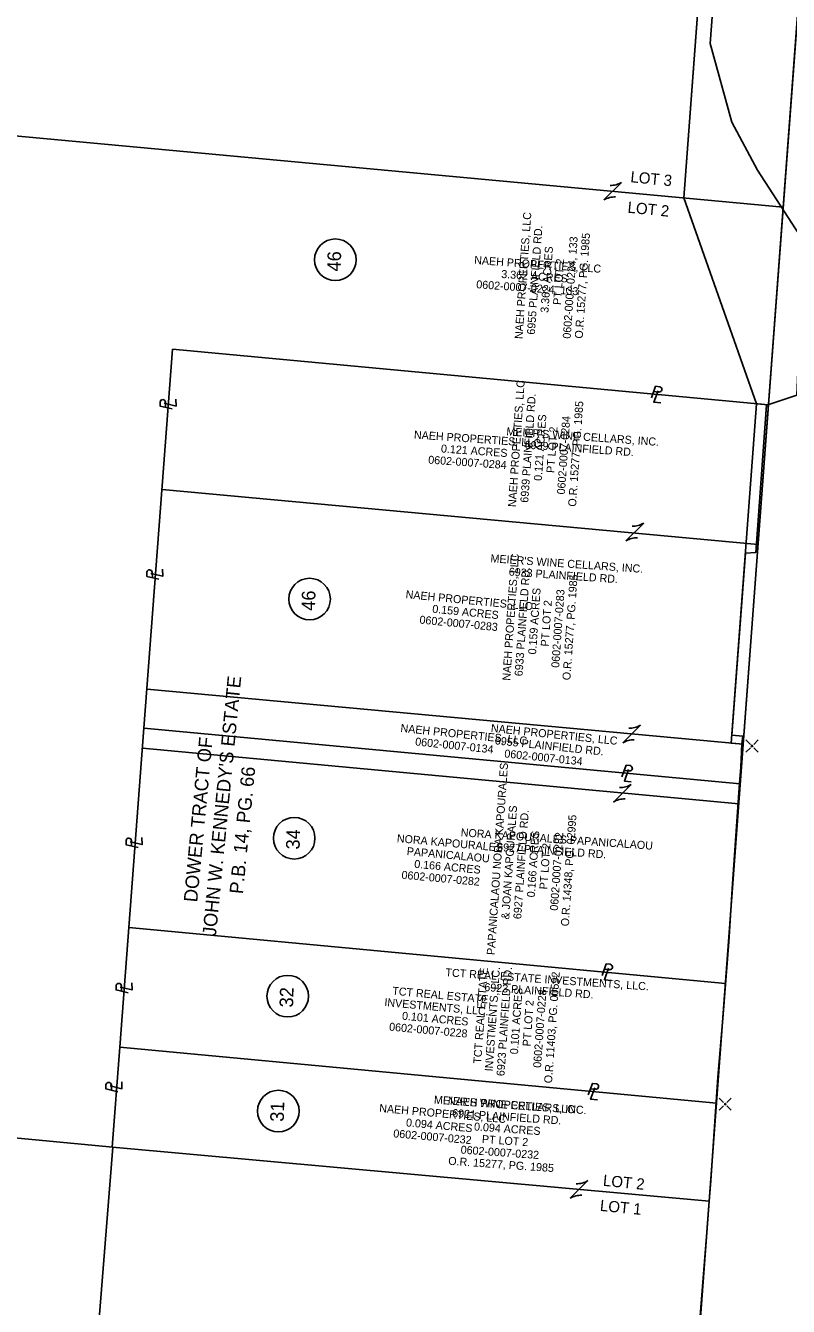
# Model space of a CAD drawing. Extents: x 204354 to 231038, y 361459 to 365260.
# Drawn here: x 220388.1 to 220578.9, y 362494.1 to 362814.2 of the extents above; entities that cross this region are included whole.
import ezdxf

# ---------------------------------------------------------------- set-up
doc = ezdxf.new("R2010")
doc.units = 0
for name, color, linetype in [('CM_Corridor_Point_Control', 7, 'Continuous'), ('Default', 7, 'Continuous'), ('DT_P_Contour_Minor', 7, 'Continuous'), ('DT_P_Contour_Text', 7, 'Continuous'), ('DT_P_Triangles', 7, 'Continuous'), ('DT_X_Contour_Minor', 7, 'Continuous'), ('MD_P_Intersection_MatchLine', 7, 'Continuous'), ('MD_P_Surface_Asphalt_Concrete_Base', 7, 'Continuous'), ('MD_P_SW_BOT', 7, 'Continuous'), ('PV_P_Walk', 7, 'Continuous'), ('SC_Shading1', 7, 'Continuous')]:
    doc.layers.add(name, color=color, linetype=linetype)

msp = doc.modelspace()

# ---------------------------------------------------------------- linework, layer by layer
at = {"layer": 'DT_P_Contour_Text'}
for centre in [(220465.57, 362755.66), (220459.14, 362670.86), (220455.29, 362611.08), (220453.67, 362571.61), (220451.33, 362542.88)]:
    msp.add_circle(centre, 5.2, dxfattribs=at)
at = {"layer": 'DT_P_Triangles'}
msp.add_lwpolyline([(220574.42, 363010.6), (220559.33, 362809.74), (220564.76, 362790.07), (220571.14, 362778.03), (220582.68, 362760.32), (220581, 362721.86), (220574.51, 362719.65), (220573.39, 362719.33), (220570.75, 362682.52), (220568.14, 362682.31), (220564.75, 362636.86), (220567.45, 362636.61), (220567.26, 362634.64), (220567.01, 362628.84), (220566.63, 362624.87), (220564.92, 362599.67), (220563.95, 362585.17), (220562.45, 362566.05), (220561.26, 362551.34), (220559.45, 362525.52), (220558.99, 362519.33), (220558.41, 362511.57), (220556.32, 362485.49)], dxfattribs=at)
at = {"layer": 'MD_P_Intersection_MatchLine'}
for p, q in [((220552.71, 362771.16), (220570.06, 363003.79)), ((220552.71, 362771.16), (220570.93, 362719.68)), ((220573.92, 362719.4), (220570.93, 362719.68))]:
    msp.add_line(p, q, dxfattribs=at)
at = {"layer": 'MD_P_Surface_Asphalt_Concrete_Base'}
for p, q in [((220568.27, 362635.64), (220569.37, 362634.55)), ((220570.2, 362634.55), (220571.29, 362635.64)), ((220568.27, 362632.62), (220569.37, 362633.72)), ((220570.2, 362633.72), (220571.29, 362632.62)), ((220561.57, 362546.12), (220562.66, 362545.03)), ((220563.49, 362545.03), (220564.58, 362546.12)), ((220561.57, 362543.1), (220562.66, 362544.19)), ((220563.49, 362544.19), (220564.58, 362543.1))]:
    msp.add_line(p, q, dxfattribs=at)
for centre in [(220569.78, 362634.14), (220563.08, 362544.62)]:
    msp.add_circle(centre, 0.17, dxfattribs=at)
at = {"layer": 'MD_P_SW_BOT'}
for p, q in [((220577.61, 362768.85), (220225.01, 362801.43)), ((220532.75, 362770.61), (220537.17, 362775.02)), ((220534.96, 362772.81), (220534.96, 362772.81)), ((220424.82, 362733.35), (220417.69, 362638.61)), ((220573.92, 362719.4), (220424.82, 362733.35)), ((220545.18, 362722.72), (220546.47, 362722.6)), ((220545.92, 362722.02), (220545.92, 362722.02)), ((220423.14, 362718.76), (220423.11, 362720.05)), ((220423.74, 362719.57), (220423.74, 362719.57)), ((220571.31, 362684.5), (220422.28, 362698.27)), ((220538.26, 362685.43), (220542.69, 362689.84)), ((220540.48, 362687.64), (220540.48, 362687.64)), ((220419.82, 362676.2), (220419.78, 362677.5)), ((220420.42, 362677.02), (220420.42, 362677.02)), ((220567.59, 362634.61), (220418.56, 362648.38)), ((220411.68, 362558.84), (220417.69, 362638.61)), ((220417.69, 362638.61), (220566.85, 362624.67)), ((220537.44, 362634.94), (220541.87, 362639.35)), ((220539.65, 362637.15), (220539.65, 362637.15)), ((220417.31, 362633.63), (220566.47, 362619.68)), ((220537.82, 362628.01), (220539.11, 362627.89)), ((220538.56, 362627.31), (220538.56, 362627.31)), ((220535.14, 362620.13), (220539.57, 362624.54)), ((220537.36, 362622.33), (220537.36, 362622.33)), ((220414.64, 362609.15), (220414.61, 362610.44)), ((220415.24, 362609.97), (220415.24, 362609.97)), ((220563.16, 362574.8), (220413.94, 362588.75)), ((220532.83, 362578.33), (220534.12, 362578.21)), ((220533.57, 362577.64), (220533.57, 362577.64)), ((220412.14, 362572.84), (220412.1, 362574.13)), ((220412.74, 362573.65), (220412.74, 362573.65)), ((220146.03, 362558.58), (220409.9, 362533.9)), ((220411.68, 362558.84), (220409.8, 362533.91)), ((220560.9, 362544.89), (220411.68, 362558.84)), ((220409.6, 362548.1), (220409.57, 362549.4)), ((220410.2, 362548.92), (220410.2, 362548.92)), ((220529.37, 362548.46), (220530.66, 362548.34)), ((220530.11, 362547.77), (220530.11, 362547.77)), ((220409.9, 362533.9), (220398.1, 362383.18)), ((220409.82, 362533.91), (220559.06, 362520.33)), ((220524.3, 362521.08), (220528.72, 362525.5)), ((220526.51, 362523.29), (220526.51, 362523.29))]:
    msp.add_line(p, q, dxfattribs=at)
for points in [[(220544.61, 362721.17), (220545.66, 362724.05), (220546.69, 362723.95)], [(220422.78, 362719.81), (220425.76, 362719.11), (220425.71, 362720.85)], [(220546.27, 362722.95), (220545.21, 362720.08), (220546.95, 362719.92)], [(220424.75, 362718.38), (220421.76, 362719.08), (220421.73, 362720.11)], [(220421.42, 362675.83), (220418.44, 362676.53), (220418.41, 362677.56)], [(220419.45, 362677.26), (220422.43, 362676.56), (220422.38, 362678.3)], [(220537.26, 362626.46), (220538.31, 362629.34), (220539.34, 362629.24)], [(220538.92, 362628.24), (220537.85, 362625.37), (220539.59, 362625.21)], [(220416.25, 362608.77), (220413.26, 362609.47), (220413.23, 362610.5)], [(220414.28, 362610.21), (220417.26, 362609.5), (220417.2, 362611.25)], [(220532.27, 362576.78), (220533.32, 362579.66), (220534.35, 362579.57)], [(220533.93, 362578.57), (220532.86, 362575.7), (220534.6, 362575.53)], [(220413.74, 362572.46), (220410.75, 362573.16), (220410.73, 362574.19)], [(220411.77, 362573.89), (220414.75, 362573.19), (220414.7, 362574.93)], [(220411.21, 362547.73), (220408.22, 362548.43), (220408.19, 362549.46)], [(220409.24, 362549.16), (220412.21, 362548.46), (220412.16, 362550.2)], [(220528.8, 362546.92), (220529.86, 362549.8), (220530.88, 362549.7)], [(220530.46, 362548.7), (220529.4, 362545.83), (220531.14, 362545.66)]]:
    msp.add_lwpolyline(points, dxfattribs=at)
for centre, radius, start, end in [((220534.42, 362779.59), 5.34, 268.4155, 301.058), ((220535.5, 362766.04), 5.34, 88.4155, 121.058), ((220546.53, 362723.28), 0.69, 265.1289, 75.986), ((220422.42, 362720.03), 0.69, 2.1187, 172.9759), ((220539.93, 362694.42), 5.34, 268.4155, 301.058), ((220541.02, 362680.86), 5.34, 88.4155, 121.058), ((220419.09, 362677.48), 0.69, 2.1187, 172.9759), ((220539.11, 362643.93), 5.34, 268.4155, 301.058), ((220540.19, 362630.37), 5.34, 88.4155, 121.058), ((220539.17, 362628.57), 0.69, 265.1289, 75.986), ((220536.81, 362629.11), 5.34, 268.4155, 301.058), ((220537.9, 362615.56), 5.34, 88.4155, 121.058), ((220413.92, 362610.42), 0.69, 2.1187, 172.9759), ((220534.18, 362578.9), 0.69, 265.1289, 75.986), ((220411.41, 362574.11), 0.69, 2.1187, 172.9759), ((220408.88, 362549.37), 0.69, 2.1187, 172.9759), ((220530.72, 362549.03), 0.69, 265.1289, 75.986), ((220525.96, 362530.07), 5.34, 268.4961, 301.1387), ((220527.06, 362516.52), 5.34, 88.4961, 121.1387)]:
    msp.add_arc(centre, radius, start, end, dxfattribs=at)
at = {"layer": 'PV_P_Walk'}
msp.add_line((220534.47, 362190.67), (220633.24, 363514.5), dxfattribs=at)
at = {"layer": 'SC_Shading1'}
for points in [[(220573.92, 362719.4), (220570.93, 362719.68), (220552.71, 362771.16), (220570.06, 363003.79), (220594.96, 363001.49)], [(220567.59, 362634.61), (220564.6, 362634.88), (220570.93, 362719.68), (220573.92, 362719.4)]]:
    msp.add_lwpolyline(points, close=True, dxfattribs=at)

# ---------------------------------------------------------------- texts
at = {"layer": 'CM_Corridor_Point_Control'}
for s, p in [("MEIER'S WINE CELLARS, INC.", (220508.3, 362711.81)), ('6939 PLAINFIELD RD.', (220512.88, 362708.48)), ("MEIER'S WINE CELLARS, INC.", (220504.33, 362680.07)), ('6933 PLAINFIELD RD.', (220508.9, 362676.74)), ('NORA KAPOURALES PAPANICALAOU', (220496.89, 362611.57)), ('6927 PLAINFIELD RD.', (220505.99, 362607.93)), ('TCT REAL ESTATE INVESTMENTS, LLC.', (220493.06, 362576.6)), ('6923 PLAINFIELD RD.', (220502.79, 362572.91)), ("MEIER'S WINE CELLARS, INC.", (220490.18, 362544.77)), ('6921 PLAINFIELD RD.', (220494.75, 362541.44))]:
    msp.add_text(s, height=2, rotation=356, dxfattribs=at).set_placement(p)
at = {"layer": 'Default'}
for s, p in [('LOT 3', (220539.28, 362775.06)), ('LOT 2', (220538.57, 362767.44))]:
    msp.add_text(s, height=2.8, rotation=354.3411, dxfattribs=at).set_placement(p)
at = {"layer": 'DT_P_Contour_Minor'}
for s, height, rotation, p in [('NAEH PROPERTIES, LLC', 2, 86, (220512.38, 362735.8)), ('6955 PLAINFIELD RD.', 2, 86, (220515.47, 362736.9)), ('0602-0007-0224, 133', 2, 86, (220524.42, 362735.89)), ('O.R. 15277, PG. 1985', 2, 86, (220527.43, 362735.91)), (' 3.362 ACRES', 2, 86, (220518.8, 362741.61)), ('PT LOT 2', 2, 86, (220522, 362744.32)), ('NAEH PROPERTIES, LLC', 2, 86, (220510.73, 362693.8)), ('6939 PLAINFIELD RD.', 2, 86, (220513.81, 362694.89)), ('O.R. 15277, PG. 1985', 2, 86, (220525.77, 362693.9)), (' 0.121 ACRES', 2, 86, (220517.15, 362699.61)), ('0602-0007-0284', 2, 86, (220522.98, 362696.96)), ('PT LOT 2', 2, 86, (220520.34, 362702.32)), ('NAEH PROPERTIES, LLC', 2, 86, (220509.3, 362650.42)), ('6933 PLAINFIELD RD.', 2, 86, (220512.38, 362651.52)), ('O.R. 15277, PG. 1985', 2, 86, (220524.34, 362650.53)), (' 0.159 ACRES', 2, 86, (220515.72, 362656.23)), ('0602-0007-0283', 2, 86, (220521.55, 362653.64)), ('PT LOT 2', 2, 86, (220518.92, 362658.94)), ("JOHN W. KENNEDY'S ESTATE", 3.4, 84.4086, (220435.71, 362586.51)), ('NAEH PROPERTIES, LLC', 2, 354.1177, (220504.4, 362637.68)), ('DOWER TRACT OF', 3.4, 84.5785, (220431.03, 362594.99)), ('6955 PLAINFIELD RD.', 2, 354.1177, (220505.39, 362634.57)), ('0602-0007-0134', 2, 354.1177, (220507.77, 362631.3)), ('14, PG. 66', 3.4, 84.4086, (220443.46, 362607.19)), ('PAPANICALAOU NORA KAPOURALES ', 2, 86, (220505.42, 362581.84)), ('& JOAN KAPOURALES', 2, 86, (220509.05, 362590.73)), ('6927 PLAINFIELD RD.', 2, 86, (220512.06, 362590.81)), ('O.R. 14348, PG. 02995', 2, 86, (220523.96, 362589.02)), (' 0.166 ACRES', 2, 86, (220515.4, 362595.52)), ('0602-0007-0282', 2, 86, (220521.23, 362592.92)), ('PT LOT 2', 2, 86, (220518.59, 362598.23)), ('P.B.', 3.4, 84.4086, (220442.47, 362597.04)), ('TCT REAL ESTATE ', 2, 86, (220502.06, 362554.67)), ('INVESTMENTS, LLC.', 2, 86, (220504.93, 362552.76)), ('6923 PLAINFIELD RD.', 2, 86, (220507.85, 362551.57)), ('O.R. 11403, PG. 00592', 2, 86, (220519.76, 362549.78)), (' 0.101 ACRES', 2, 86, (220511.19, 362556.29)), ('PT LOT 2', 2, 86, (220514.39, 362558.99)), ('0602-0007-0228', 2, 86, (220517.02, 362553.66)), ('NAEH PROPERTIES, LLC', 2, 356, (220493.66, 362544.52)), ('6921 PLAINFIELD RD.', 2, 356, (220494.75, 362541.44)), (' 0.094 ACRES', 2, 356, (220499.47, 362538.1)), ('PT LOT 2', 2, 356, (220502.18, 362534.91)), ('0602-0007-0232', 2, 356, (220496.87, 362532.27)), ('O.R. 15277, PG. 1985', 2, 356, (220493.76, 362529.48)), ('LOT 2', 2.8, 354.3411, (220532.42, 362524.22)), ('LOT 1', 2.8, 354.3411, (220531.66, 362517.96))]:
    msp.add_text(s, height=height, rotation=rotation, dxfattribs=at).set_placement(p)
at = {"layer": 'DT_P_Contour_Text'}
for s, p in [('46', (220466.9, 362752.7)), ('46', (220460.48, 362667.9)), ('34', (220456.63, 362608.23)), ('32', (220455, 362568.75)), ('31', (220452.67, 362540.17))]:
    msp.add_text(s, height=3.4, rotation=88.3143, dxfattribs=at).set_placement(p)
at = {"layer": 'DT_X_Contour_Minor'}
for s, rotation, p in [('NAEH PROPERTIES, LLC', 356, (220500.25, 362754.62)), (' 3.362 ACRES', 356, (220506.28, 362751.19)), ('0602-0007-0224, 133', 356, (220500.77, 362748.57)), ('NAEH PROPERTIES, LLC', 356, (220485.18, 362711)), (' 0.121 ACRES', 356, (220491.2, 362707.57)), ('0602-0007-0284', 356, (220488.76, 362704.73)), ('NAEH PROPERTIES, LLC', 354.4548, (220483.09, 362671.11)), ('0602-0007-0283', 354.4548, (220486.56, 362664.75)), (' 0.159 ACRES', 354.4548, (220489.02, 362667.53)), ('NAEH PROPERTIES, LLC', 354.1177, (220481.8, 362637.68)), ('0602-0007-0134', 354.1177, (220485.48, 362634.29)), ('NORA KAPOURALES ', 354.7918, (220480.9, 362610.12)), ('PAPANICALAOU', 354.7918, (220483.37, 362606.89)), (' 0.166 ACRES', 354.7918, (220484.51, 362603.77)), ('0602-0007-0282', 354.7918, (220482.06, 362600.98)), ('TCT REAL ESTATE ', 354.8041, (220479.75, 362571.99)), ('INVESTMENTS, LLC.', 354.8041, (220477.78, 362569.15)), (' 0.101 ACRES', 354.8041, (220481.45, 362565.81)), ('0602-0007-0228', 354.8041, (220478.97, 362563.02)), ('NAEH PROPERTIES, LLC', 354.9648, (220476.49, 362542.67)), (' 0.094 ACRES', 354.9648, (220482.45, 362539.13)), ('0602-0007-0232', 354.9648, (220480.01, 362536.34))]:
    msp.add_text(s, height=2, rotation=rotation, dxfattribs=at).set_placement(p)

doc.saveas('drawing.dxf')
